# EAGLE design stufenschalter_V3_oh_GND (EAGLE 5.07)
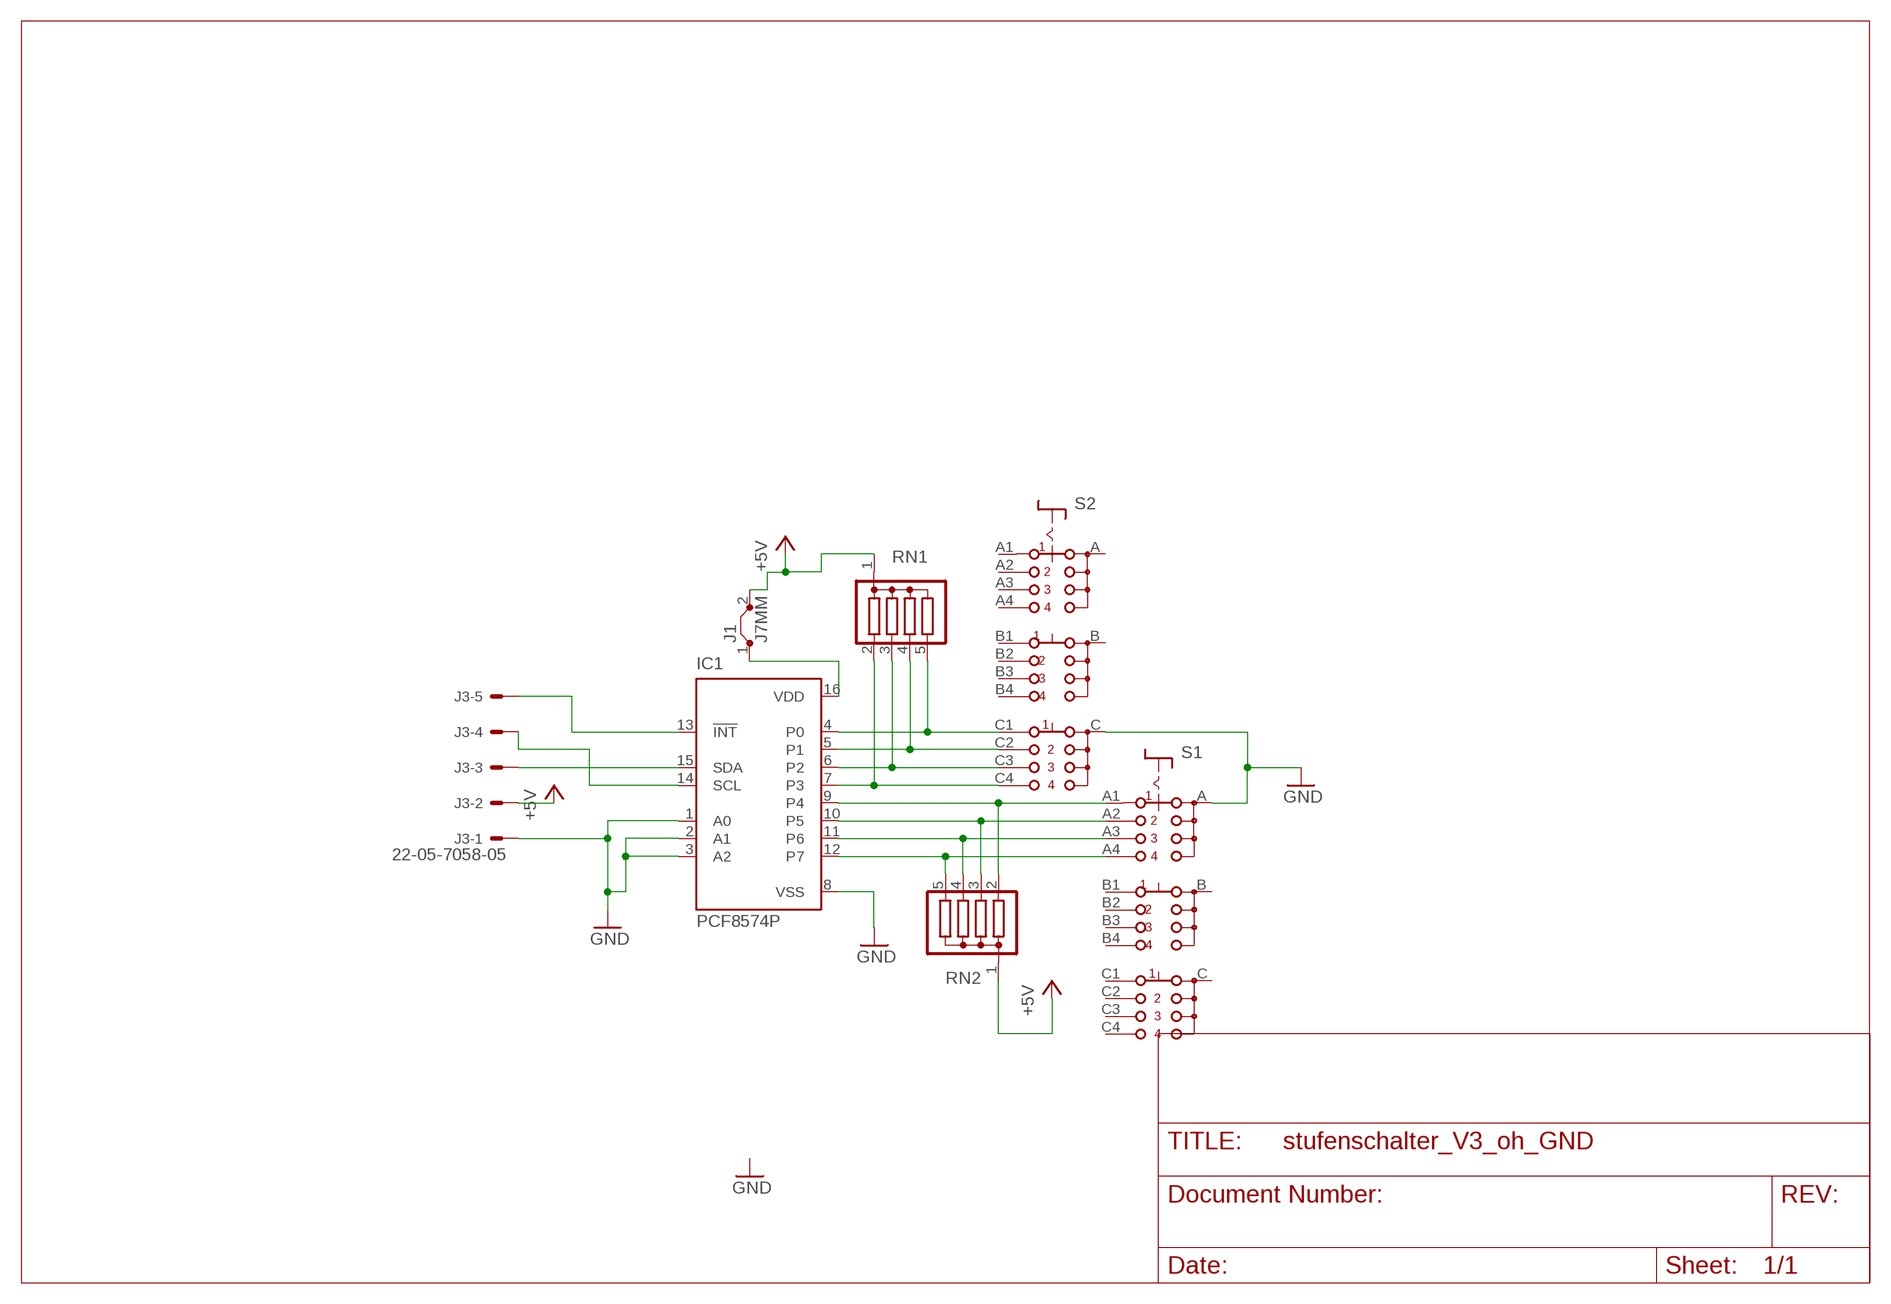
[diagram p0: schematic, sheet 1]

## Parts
IC1  PCF8574P  [DIL16]
J1  J7MM  [07]
J3  22-05-7058-05  [7395-05]
RN1  G04R  [SIL5]
RN2  G04R  [SIL5]
S1  CK103X04  [CK103X04]
S2  CK103X04  [CK103X04]

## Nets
+5V: J1.2 J3.2 RN1.1 RN2.1
GND: IC1.1(A0) IC1.2(A1) IC1.3(A2) IC1.8(VSS) J3.1 S1.A S2.C
N$1: IC1.16(VDD) J1.1
N$2: IC1.4(P0) RN1.5 S2.C1
N$3: IC1.5(P1) RN1.4 S2.C2
N$4: IC1.6(P2) RN1.3 S2.C3
N$5: IC1.7(P3) RN1.2 S2.C4
N$6: IC1.15(SDA) J3.3
N$7: IC1.13(!INT) J3.5
N$9: IC1.12(P7) RN2.5 S1.A4
N$12: IC1.14(SCL) J3.4
N$14: IC1.9(P4) RN2.2 S1.A1
N$15: IC1.10(P5) RN2.3 S1.A2
N$16: IC1.11(P6) RN2.4 S1.A3
Unconnected: S1.B S1.B1 S1.B2 S1.B3 S1.B4 S1.C S1.C1 S1.C2 S1.C3 S1.C4 S2.A S2.A1 S2.A2 S2.A3 S2.A4 S2.B S2.B1 S2.B2 S2.B3 S2.B4

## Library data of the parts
IC1 = micro-philips:PCF8574: I2C-Bus Remote 8-bit I/O expander http://www.semiconductors.philips.com/acrobat_download/datasheets/PCF8574_4.pdf
J1 = jumper:J: Bridge
J3 = con-molex:22-?-05: CONNECTOR wire to board 2.54 mm (.1 inch) pitch header
RN1 RN2 = resistor-sil:G04R: SIL RESISTOR
S1 S2 = switch:CK103X04: ROTARY SWITCH C&K

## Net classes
0 default: width 1.016 mm, clearance 0.965 mm

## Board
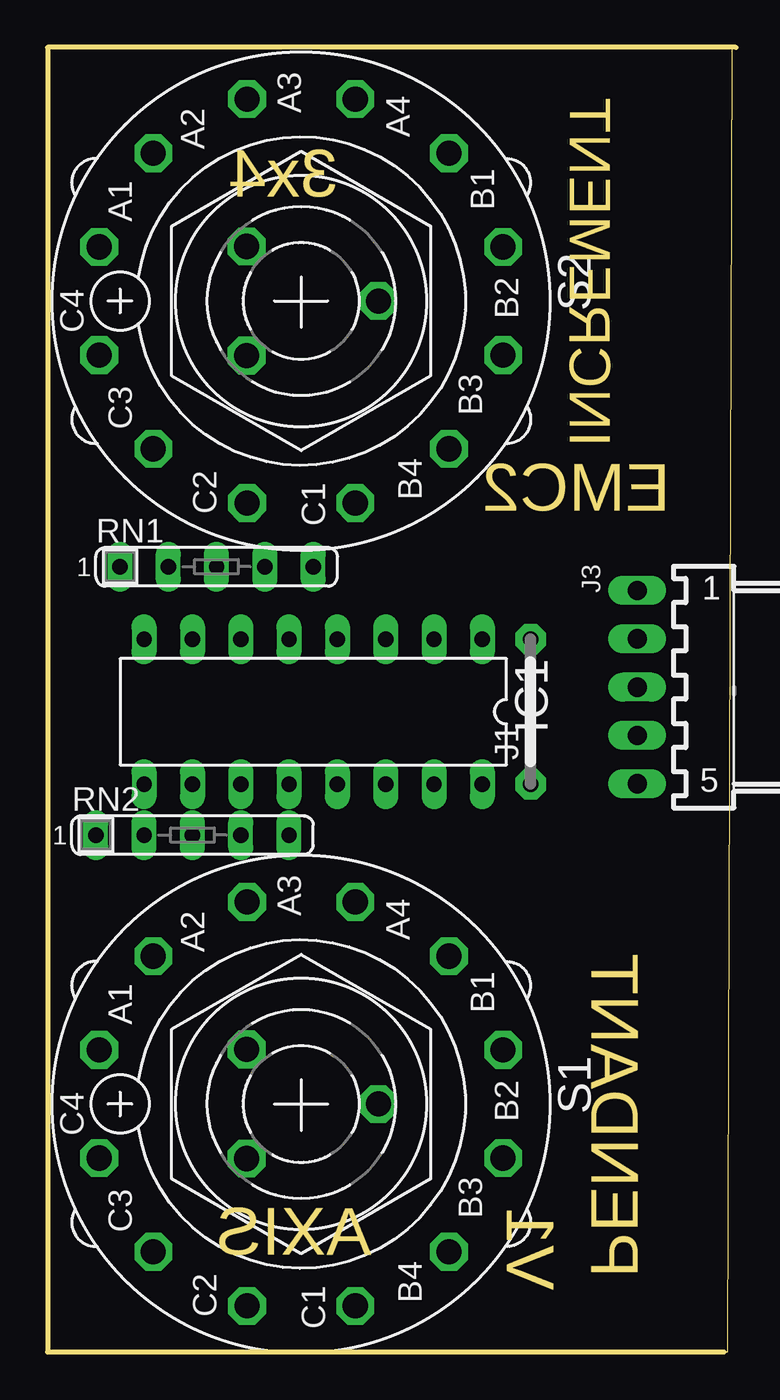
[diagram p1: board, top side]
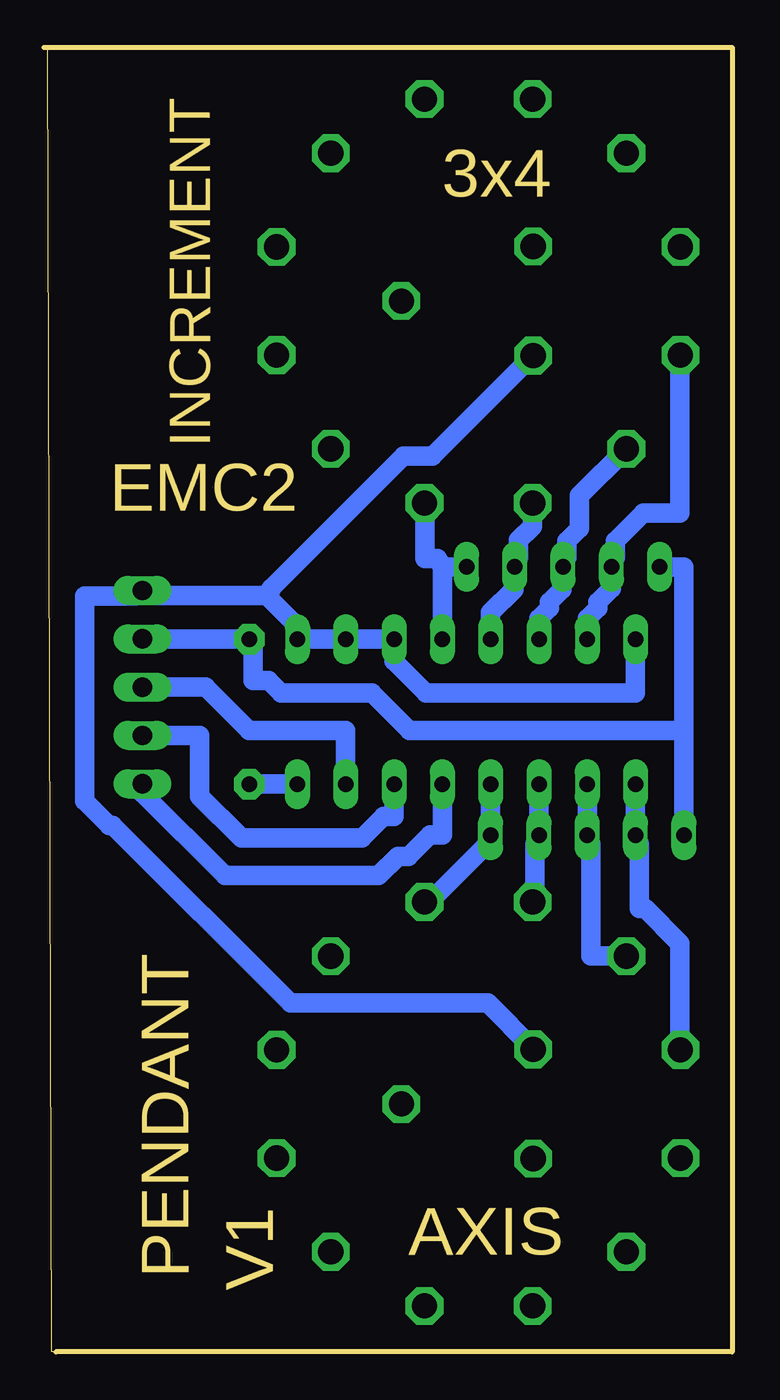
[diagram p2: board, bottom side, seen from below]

Size 36 x 68.57 mm. Coordinates in mm from the lower left corner, seen from the top.
Outline: 0,0 35.77,0 36,68.57 0,68.57 0,0
Copper layers (1*16): Top 0.035mm / dielectric 1.5mm / Bottom 0.035mm
Design rules "default": minimum track width 10mil, minimum drill 24mil, track to track 8mil, track to pad 8mil, pad to pad 8mil, via to via 8mil, smd to smd 8mil, copper to edge 40mil, drill to drill 8mil, minimum pad ring 10mil, minimum via ring 8mil, stop-mask expansion 4mil, vias tented up to drill 0mil, thermal gap 10mil
Milling: 3 lines

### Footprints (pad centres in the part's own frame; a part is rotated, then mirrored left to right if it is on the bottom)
DIL16 = drill 0.813 long: 1 -8.89,-3.81; 2 -6.35,-3.81; 3 -3.81,-3.81; 4 -1.27,-3.81; 5 1.27,-3.81; 6 3.81,-3.81; 7 6.35,-3.81; 8 8.89,-3.81; 9 8.89,3.81; 10 6.35,3.81; 11 3.81,3.81; 12 1.27,3.81; 13 -1.27,3.81; 14 -3.81,3.81; 15 -6.35,3.81; 16 -8.89,3.81
07 = drill 0.813 pad 1.6 octagon: 1 -3.81,0; 2 3.81,0
7395-05 = drill 1.016 long: 1 5.08,0; 2 2.54,0; 3 0,0; 4 -2.54,0; 5 -5.08,0
SIL5 = drill 0.813 long: 1 -5.08,0; 2 -2.54,0; 3 0,0; 4 2.54,0; 5 5.08,0
CK103X04 = drill 1.321 octagon: A -2.87,-2.87; A1 -2.845,-10.617; A2 -7.772,-7.772; A3 -10.617,-2.845; A4 -10.617,2.845; B 0,4.059; B1 -7.772,7.772; B2 -2.845,10.617; B3 2.845,10.617; B4 7.772,7.772; C 2.87,-2.87; C1 10.617,2.845; C2 10.617,-2.845; C3 7.772,-7.772; C4 2.845,-10.617

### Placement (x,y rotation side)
IC1  13.97,33.66 180 top
J1  25.4,33.66 90 top
J3  31.01,34.95 90 top
RN1  8.89,41.27 0 top
RN2  7.62,27.17 0 top
S1  13.34,13.04 270 top
S2  13.34,55.24 270 top

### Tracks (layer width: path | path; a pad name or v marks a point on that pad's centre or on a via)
+5V
  Bottom 1.016: J3.2 25.4,37.49 J1.2 25.2,36.98 25.2,35.31 24.38,35.31 23.72,34.65 18.95,34.65 16.97,32.66 2.54,32.66 | 2.54,32.66 2.54,41.25 3.81,41.25 RN1.1 | RN2.1 2.54,32.66
GND
  Bottom 1.016: IC1.8 5.08,34.65 16.1,34.65 17.78,36.32 IC1.3 18.24,37.49 20.32,37.49 IC1.2 20.78,37.49 22.86,37.49 IC1.1 22.66,37.95 24.49,39.78 | 24.49,39.78 30.73,39.78 30.99,40.03 J3.1 31.39,39.73 34.04,39.73 34.04,28.96 32.77,27.69 32.56,27.69 23.22,18.34 12.85,18.34 10.46,15.95 S1.A | S2.C 15.75,47.09 17.27,47.09 24.18,40.18 24.49,39.78
N$1
  Bottom 1.016: IC1.16 22.86,29.87 25.4,29.87 J1.1
N$2
  Bottom 1.016: 15.24,41.25 13.97,41.25 RN1.5 | IC1.4 15.24,41.25 | S2.C1 16.15,44.6 16.15,41.71 15.49,41.71 15.24,41.25
N$3
  Bottom 1.016: IC1.5 12.7,38.86 11.48,40.08 11.48,41.25 11.43,41.25 RN1.4 11.23,41.76 11.23,42.67 10.52,43.38 10.52,44.6 S2.C2
N$4
  Bottom 1.016: IC1.6 10.16,38.56 9.6,39.12 9.6,39.42 8.94,40.08 8.94,41.25 8.89,41.25 RN1.3 8.69,41.76 8.69,42.62 8.03,43.28 8.03,45.01 S2.C3
N$5
  Bottom 1.016: IC1.7 7.62,38.56 7.06,39.12 7.06,39.42 6.35,40.13 RN1.2 6.15,41.76 6.15,42.62 4.67,44.09 2.74,44.09 2.74,52.38 S2.C4
N$6
  Bottom 1.016: IC1.15 20.32,32.66 25.4,32.66 27.69,34.95 J3.3
N$7
  Bottom 1.016: IC1.13 15.24,27.18 15.9,27.18 17.02,26.06 17.58,26.06 18.59,25.04 26.67,25.04 30.99,29.36 30.99,29.87 J3.5
N$9
  Bottom 1.016: IC1.12 RN2.5 12.9,26.67 15.9,23.67 16.15,23.67 S1.A4
N$12
  Bottom 1.016: IC1.14 17.78,28.14 18.34,28.14 19.46,27.03 25.81,27.03 27.99,29.21 27.99,32.41 J3.4
N$14
  Bottom 1.016: IC1.9 RN2.2 4.88,26.67 4.88,23.32 4.57,23.32 2.74,21.49 2.74,15.9 S1.A1
N$15
  Bottom 1.016: IC1.10 RN2.3 7.42,26.67 7.42,20.83 5.59,20.83 S1.A2
N$16
  Bottom 1.016: IC1.11 RN2.4 10.36,26.67 10.36,23.67 10.46,23.67 S1.A3

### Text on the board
Milling: INCREMENT | 3x4 | EMC2 | PENDANT | AXIS | V1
